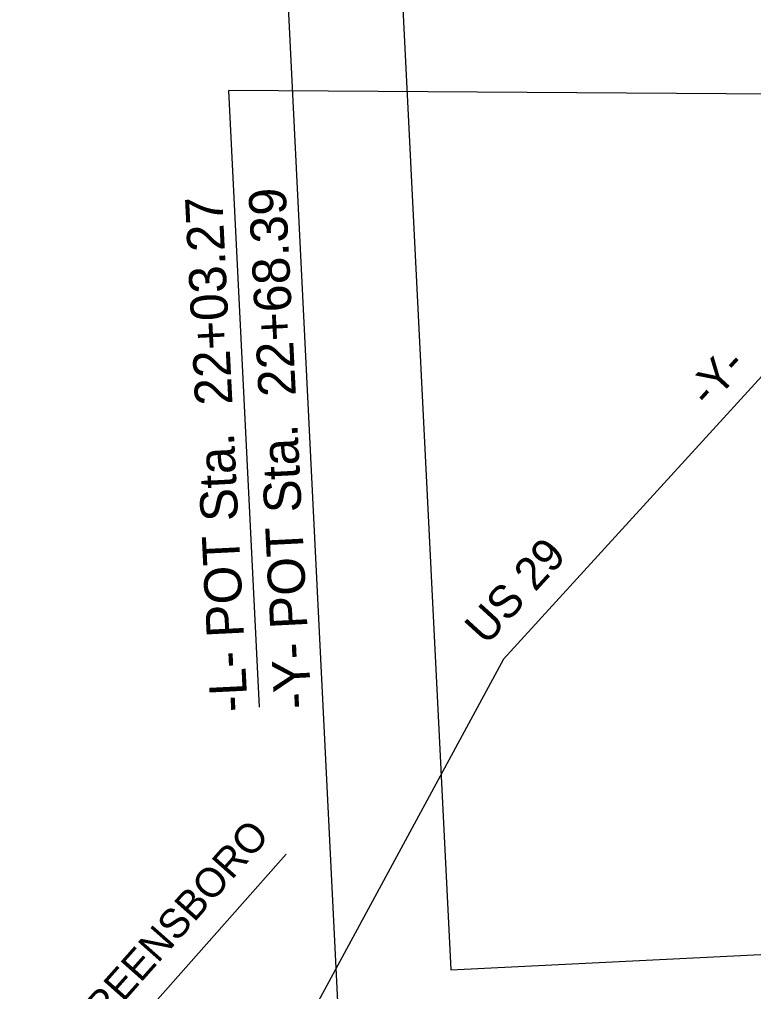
# Model space of a CAD drawing. Extents: x 1805231 to 1809482, y 908883 to 918297.
# Drawn here: x 1806820 to 1807608, y 913747 to 914790 of the extents above; entities that cross this region are included whole.
import ezdxf

# ---------------------------------------------------------------- set-up
doc = ezdxf.new("R2010")
doc.units = 0
for name, color, linetype in [('Prop Horizontal Alignment', 7, 'Continuous'), ('Prop Horizontal Alignment Station Label', 7, 'Continuous'), ('Prop Leader Line Medium', 7, 'Continuous'), ('Prop Shade Medium', 7, 'Continuous'), ('Scratch_Level_0', 7, 'Continuous')]:
    doc.layers.add(name, color=color, linetype=linetype)

msp = doc.modelspace()

# ---------------------------------------------------------------- linework, layer by layer
at = {"layer": 'Prop Horizontal Alignment'}
msp.add_line((1807339.4, 914103.4), (1808518.2, 915396.8), dxfattribs=at)
at = {"layer": 'Prop Horizontal Alignment Station Label'}
for p, q in [((1807890.7, 914708.2), (1807044.4, 914714.2)), ((1807077.3, 914051.9), (1807044.4, 914714.2)), ((1807339.4, 914103.4), (1807097.7, 913656.9))]:
    msp.add_line(p, q, dxfattribs=at)
at = {"layer": 'Prop Leader Line Medium'}
msp.add_line((1806849.7, 913604.7), (1807106.1, 913893.9), dxfattribs=at)
at = {"layer": 'Prop Shade Medium'}
msp.add_lwpolyline([(1807282.7, 913769.8), (1808331.4, 913821.9), (1808257.3, 915314.8), (1807444, 915192.5), (1807212.6, 915181), (1807218.2, 915068.2)], close=True, dxfattribs=at)
at = {"layer": 'Scratch_Level_0'}
msp.add_lwpolyline([(1807178.4, 913396.6), (1807021.1, 916565.5), (1808571, 916642.5), (1808728.3, 913473.6)], close=True, dxfattribs=at)

# ---------------------------------------------------------------- texts
at = {"layer": 'Prop Horizontal Alignment Station Label'}
for s, height, rotation, p in [('-Y- POT Sta.  22+68.39', 40, 92.8422, (1807133.2, 914050.9)), ('-L- POT Sta.  22+03.27', 40, 92.8422, (1807064.8, 914047.5)), ('-Y-', 35, 47.6532, (1807559.7, 914372.4)), ('US 29', 35, 47.6532, (1807320.8, 914117.3))]:
    msp.add_text(s, height=height, rotation=rotation, dxfattribs=at).set_placement(p)
at = {"layer": 'Prop Leader Line Medium'}
msp.add_text('TO GREENSBORO', height=31.5, rotation=48.4457, dxfattribs=at).set_placement((1806842.6, 913634.5))

doc.saveas('drawing.dxf')
